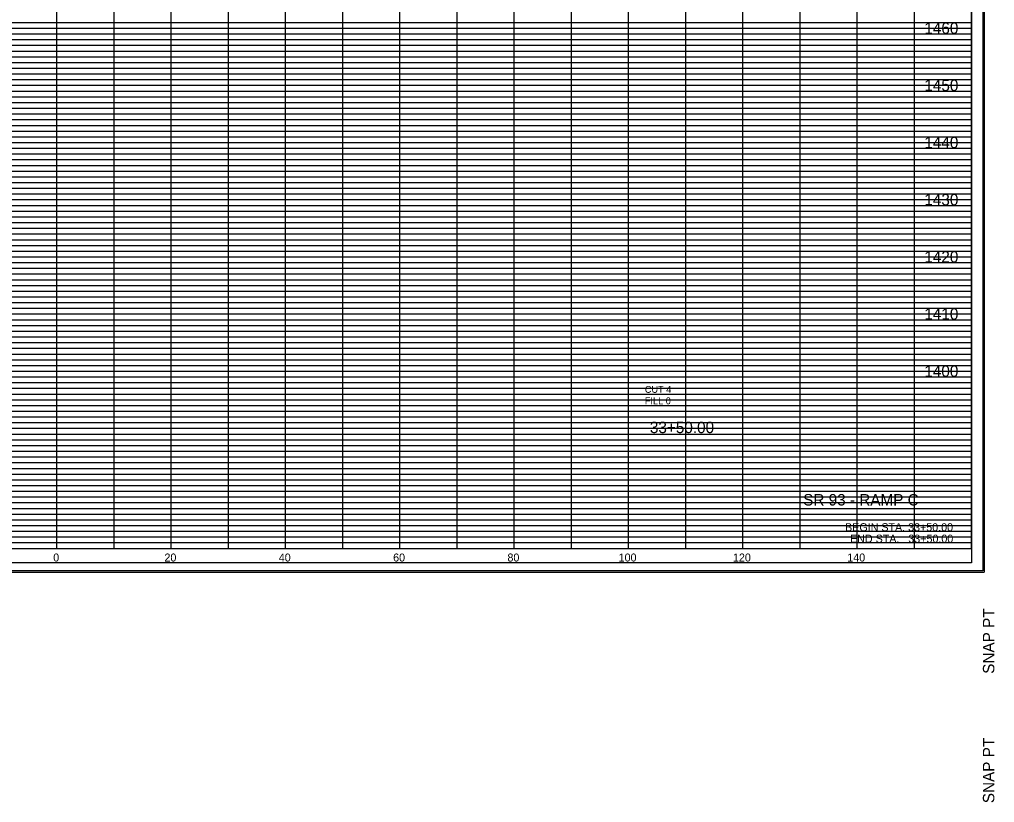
# Model space of a CAD drawing. Extents: x 980 to 2064, y 978 to 2267.
# Drawn here: x 1523.4 to 1694, y 1995.5 to 2132.5 of the extents above; entities that cross this region are included whole.
import ezdxf

# ---------------------------------------------------------------- set-up
doc = ezdxf.new("R2010")
doc.units = 0
for name, color, linetype in [('Default', 7, 'Continuous'), ('DESIGN - SHEET - Corner Text', 7, 'Continuous'), ('DESIGN - SHEET - Light Grid', 7, 'Continuous'), ('DESIGN - SHEET - Linework', 7, 'Continuous'), ('DESIGN - SHEET - Plot Shape', 7, 'Continuous'), ('DESIGN - TYPICAL - Text', 7, 'Continuous')]:
    doc.layers.add(name, color=color, linetype=linetype)

# ---------------------------------------------------------------- blocks, each defined once
blk = doc.blocks.new('XSTSHT')
at = {"layer": 'DESIGN - SHEET - Light Grid'}
for p, q in [((8, 9.2), (16, 9.2)), ((8, 9.1), (16, 9.1)), ((16, 9.2), (24, 9.2)), ((16, 9.1), (24, 9.1)), ((24, 9.2), (32, 9.2)), ((24, 9.1), (32, 9.1)), ((8, 8.9), (16, 8.9)), ((16, 8.9), (24, 8.9)), ((24, 8.9), (32, 8.9)), ((8, 8.8), (16, 8.8)), ((8, 8.7), (16, 8.7)), ((16, 8.8), (24, 8.8)), ((16, 8.7), (24, 8.7)), ((24, 8.8), (32, 8.8)), ((24, 8.7), (32, 8.7)), ((8, 8.6), (16, 8.6)), ((16, 8.6), (24, 8.6)), ((24, 8.6), (32, 8.6)), ((8, 8.5), (16, 8.5)), ((8, 8.4), (16, 8.4)), ((16, 8.5), (24, 8.5)), ((16, 8.4), (24, 8.4)), ((24, 8.5), (32, 8.5)), ((24, 8.4), (32, 8.4)), ((8, 8.3), (16, 8.3)), ((8, 8.2), (16, 8.2)), ((16, 8.3), (24, 8.3)), ((16, 8.2), (24, 8.2)), ((24, 8.3), (32, 8.3)), ((24, 8.2), (32, 8.2)), ((8, 8.1), (16, 8.1)), ((16, 8.1), (24, 8.1)), ((24, 8.1), (32, 8.1)), ((8, 7.9), (16, 7.9)), ((16, 7.9), (24, 7.9)), ((24, 7.9), (32, 7.9)), ((8, 7.8), (16, 7.8)), ((8, 7.7), (16, 7.7)), ((16, 7.8), (24, 7.8)), ((16, 7.7), (24, 7.7)), ((24, 7.8), (32, 7.8)), ((24, 7.7), (32, 7.7)), ((8, 7.6), (16, 7.6)), ((16, 7.6), (24, 7.6)), ((24, 7.6), (32, 7.6)), ((8, 7.5), (16, 7.5)), ((8, 7.4), (16, 7.4)), ((16, 7.5), (24, 7.5)), ((16, 7.4), (24, 7.4)), ((24, 7.5), (32, 7.5)), ((24, 7.4), (32, 7.4)), ((8, 7.3), (16, 7.3)), ((8, 7.2), (16, 7.2)), ((16, 7.3), (24, 7.3)), ((16, 7.2), (24, 7.2)), ((24, 7.3), (32, 7.3)), ((24, 7.2), (32, 7.2)), ((8, 7.1), (16, 7.1)), ((16, 7.1), (24, 7.1)), ((24, 7.1), (32, 7.1)), ((8, 6.9), (16, 6.9)), ((16, 6.9), (24, 6.9)), ((24, 6.9), (32, 6.9)), ((8, 6.8), (16, 6.8)), ((8, 6.7), (16, 6.7)), ((16, 6.8), (24, 6.8)), ((16, 6.7), (24, 6.7)), ((24, 6.8), (32, 6.8)), ((24, 6.7), (32, 6.7)), ((8, 6.6), (16, 6.6)), ((8, 6.5), (16, 6.5)), ((16, 6.6), (24, 6.6)), ((16, 6.5), (24, 6.5)), ((24, 6.6), (32, 6.6)), ((24, 6.5), (32, 6.5)), ((8, 6.4), (16, 6.4)), ((16, 6.4), (24, 6.4)), ((24, 6.4), (32, 6.4)), ((8, 6.3), (16, 6.3)), ((8, 6.2), (16, 6.2)), ((16, 6.3), (24, 6.3)), ((16, 6.2), (24, 6.2)), ((24, 6.3), (32, 6.3)), ((24, 6.2), (32, 6.2)), ((8, 6.1), (16, 6.1)), ((16, 6.1), (24, 6.1)), ((24, 6.1), (32, 6.1)), ((8, 5.9), (16, 5.9)), ((8, 5.8), (16, 5.8)), ((16, 5.9), (24, 5.9)), ((16, 5.8), (24, 5.8)), ((24, 5.9), (32, 5.9)), ((24, 5.8), (32, 5.8)), ((8, 5.7), (16, 5.7)), ((16, 5.7), (24, 5.7)), ((24, 5.7), (32, 5.7)), ((8, 5.6), (16, 5.6)), ((8, 5.5), (16, 5.5)), ((16, 5.6), (24, 5.6)), ((16, 5.5), (24, 5.5)), ((24, 5.6), (32, 5.6)), ((24, 5.5), (32, 5.5)), ((8, 5.4), (16, 5.4)), ((8, 5.3), (16, 5.3)), ((16, 5.4), (24, 5.4)), ((16, 5.3), (24, 5.3)), ((24, 5.4), (32, 5.4)), ((24, 5.3), (32, 5.3)), ((8, 5.2), (16, 5.2)), ((16, 5.2), (24, 5.2)), ((24, 5.2), (32, 5.2)), ((8, 5.1), (16, 5.1)), ((16, 5.1), (24, 5.1)), ((24, 5.1), (32, 5.1)), ((8, 4.9), (16, 4.9)), ((8, 4.8), (16, 4.8)), ((16, 4.9), (24, 4.9)), ((16, 4.8), (24, 4.8)), ((24, 4.9), (32, 4.9)), ((24, 4.8), (32, 4.8)), ((8, 4.7), (16, 4.7)), ((16, 4.7), (24, 4.7)), ((24, 4.7), (32, 4.7)), ((8, 4.6), (16, 4.6)), ((8, 4.5), (16, 4.5)), ((16, 4.6), (24, 4.6)), ((16, 4.5), (24, 4.5)), ((24, 4.6), (32, 4.6)), ((24, 4.5), (32, 4.5)), ((8, 4.4), (16, 4.4)), ((8, 4.3), (16, 4.3)), ((16, 4.4), (24, 4.4)), ((16, 4.3), (24, 4.3)), ((24, 4.4), (32, 4.4)), ((24, 4.3), (32, 4.3)), ((8, 4.2), (16, 4.2)), ((8, 4.1), (16, 4.1)), ((16, 4.2), (24, 4.2)), ((16, 4.1), (24, 4.1)), ((24, 4.2), (32, 4.2)), ((24, 4.1), (32, 4.1)), ((8, 3.9), (16, 3.9)), ((8, 3.8), (16, 3.8)), ((16, 3.9), (24, 3.9)), ((16, 3.8), (24, 3.8)), ((24, 3.9), (32, 3.9)), ((24, 3.8), (32, 3.8)), ((8, 3.7), (16, 3.7)), ((8, 3.6), (16, 3.6)), ((16, 3.7), (24, 3.7)), ((16, 3.6), (24, 3.6)), ((24, 3.7), (32, 3.7)), ((24, 3.6), (32, 3.6)), ((8, 3.5), (16, 3.5)), ((16, 3.5), (24, 3.5)), ((24, 3.5), (32, 3.5)), ((8, 3.4), (16, 3.4)), ((8, 3.3), (16, 3.3)), ((16, 3.4), (24, 3.4)), ((16, 3.3), (24, 3.3)), ((24, 3.4), (32, 3.4)), ((24, 3.3), (32, 3.3)), ((8, 3.2), (16, 3.2)), ((8, 3.1), (16, 3.1)), ((16, 3.2), (24, 3.2)), ((16, 3.1), (24, 3.1)), ((24, 3.2), (32, 3.2)), ((24, 3.1), (32, 3.1)), ((8, 2.9), (16, 2.9)), ((16, 2.9), (24, 2.9)), ((24, 2.9), (32, 2.9)), ((8, 2.8), (16, 2.8)), ((16, 2.8), (24, 2.8)), ((24, 2.8), (32, 2.8)), ((8, 2.7), (16, 2.7)), ((8, 2.6), (16, 2.6)), ((16, 2.7), (24, 2.7)), ((16, 2.6), (24, 2.6)), ((24, 2.7), (32, 2.7)), ((24, 2.6), (32, 2.6)), ((8, 2.5), (16, 2.5)), ((8, 2.4), (16, 2.4)), ((16, 2.5), (24, 2.5)), ((16, 2.4), (24, 2.4)), ((24, 2.5), (32, 2.5)), ((24, 2.4), (32, 2.4)), ((8, 2.3), (16, 2.3)), ((16, 2.3), (24, 2.3)), ((24, 2.3), (32, 2.3)), ((8, 2.2), (16, 2.2)), ((8, 2.1), (16, 2.1)), ((16, 2.2), (24, 2.2)), ((16, 2.1), (24, 2.1)), ((24, 2.2), (32, 2.2)), ((24, 2.1), (32, 2.1)), ((8, 1.9), (16, 1.9)), ((16, 1.9), (24, 1.9)), ((24, 1.9), (32, 1.9)), ((8, 1.8), (16, 1.8)), ((16, 1.8), (24, 1.8)), ((24, 1.8), (32, 1.8)), ((8, 1.7), (16, 1.7)), ((8, 1.6), (16, 1.6)), ((16, 1.7), (24, 1.7)), ((16, 1.6), (24, 1.6)), ((24, 1.7), (32, 1.7)), ((24, 1.6), (32, 1.6)), ((8, 1.5), (16, 1.5)), ((8, 1.4), (16, 1.4)), ((16, 1.5), (24, 1.5)), ((16, 1.4), (24, 1.4)), ((24, 1.5), (32, 1.5)), ((24, 1.4), (32, 1.4)), ((8, 1.3), (16, 1.3)), ((8, 1.2), (16, 1.2)), ((16, 1.3), (24, 1.3)), ((16, 1.2), (24, 1.2)), ((24, 1.3), (32, 1.3)), ((24, 1.2), (32, 1.2)), ((8, 1.1), (16, 1.1)), ((16, 1.1), (24, 1.1)), ((24, 1.1), (32, 1.1)), ((8, 0.9), (16, 0.9)), ((16, 0.9), (24, 0.9)), ((24, 0.9), (32, 0.9)), ((8, 0.8), (16, 0.8)), ((8, 0.7), (16, 0.7)), ((16, 0.8), (24, 0.8)), ((16, 0.7), (24, 0.7)), ((24, 0.8), (32, 0.8)), ((24, 0.7), (32, 0.7)), ((8, 0.6), (16, 0.6)), ((16, 0.6), (24, 0.6)), ((24, 0.6), (32, 0.6)), ((8, 0.5), (16, 0.5)), ((8, 0.4), (16, 0.4)), ((16, 0.5), (24, 0.5)), ((16, 0.4), (24, 0.4)), ((24, 0.5), (32, 0.5)), ((24, 0.4), (32, 0.4)), ((8, 0.3), (16, 0.3)), ((8, 0.2), (16, 0.2)), ((16, 0.3), (24, 0.3)), ((16, 0.2), (24, 0.2)), ((24, 0.3), (32, 0.3)), ((24, 0.2), (32, 0.2)), ((8, 0.1), (16, 0.1)), ((16, 0.1), (24, 0.1)), ((24, 0.1), (32, 0.1))]:
    blk.add_line(p, q, dxfattribs=at)
at = {"layer": 'DESIGN - SHEET - Linework'}
for p, q in [((32.217, 21.414), (32.217, -0.414)), ((16, 0), (16, 21)), ((17, 0), (17, 21)), ((18, 0), (18, 21)), ((19, 0), (19, 21)), ((20, 0), (20, 21)), ((21, 0), (21, 21)), ((22, 0), (22, 21)), ((23, 0), (23, 21)), ((24, 0), (24, 21)), ((25, 0), (25, 21)), ((26, 0), (26, 21)), ((27, 0), (27, 21)), ((28, 0), (28, 20)), ((29, 0), (29, 20)), ((30, 0), (30, 20)), ((31, 0), (31, 20)), ((0, 9), (32, 9)), ((0, 8), (32, 8)), ((0, 7), (32, 7)), ((0, 6), (32, 6)), ((0, 5), (32, 5)), ((0, 4), (32, 4)), ((0, 3), (32, 3)), ((0, 2), (32, 2)), ((0, 1), (32, 1)), ((-1.823, -0.414), (32.217, -0.414))]:
    blk.add_line(p, q, dxfattribs=at)
blk.add_lwpolyline([(0, 21), (0, 0), (32, 0), (32, 21), (0, 21)], dxfattribs=at)
at = {"layer": 'DESIGN - SHEET - Plot Shape'}
for points in [[(-1.803, 21.394), (32.197, 21.394), (32.197, -0.394), (-1.803, -0.394)], [(-0.85, 21), (32, 21), (32, -0.25), (-0.85, -0.25)]]:
    blk.add_lwpolyline(points, close=True, dxfattribs=at)
at = {"layer": 'DESIGN - SHEET - Corner Text'}
for s, p in [('  SNAP PT', (32.397, 21.394)), ('SNAP PT  ', (32.397, -2.194))]:
    blk.add_text(s, height=0.2, rotation=90, dxfattribs=at).set_placement(p)

msp = doc.modelspace()

# ---------------------------------------------------------------- block references
at = {"layer": 'Default', "xscale": 10, "yscale": 10}
for p in [(1370, 2040), (1370, 1780)]:
    msp.add_blockref('XSTSHT', p, dxfattribs=at)

# ---------------------------------------------------------------- texts
at = {"layer": 'Default'}
for s, height, p in [('     1460     ', 2, (1678.01, 2130)), ('     1450     ', 2, (1678.01, 2120)), ('     1440     ', 2, (1678.01, 2110)), ('     1430     ', 2, (1678.01, 2100)), ('     1420     ', 2, (1678.01, 2090)), ('     1410     ', 2, (1678.01, 2080)), ('     1400     ', 2, (1678.01, 2070)), ('     33+50.00     ', 2, (1630, 2060.16)), ('     0     ', 1.4, (1526.74, 2037.7)), ('     0     ', 1.4, (1526.74, 2037.7)), ('     20     ', 1.4, (1546.2, 2037.7)), ('     40     ', 1.4, (1566.2, 2037.7)), ('     60     ', 1.4, (1586.2, 2037.7)), ('     80     ', 1.4, (1606.2, 2037.7)), ('     100     ', 1.4, (1625.65, 2037.7)), ('     120     ', 1.4, (1645.65, 2037.7)), ('     140     ', 1.4, (1665.65, 2037.7))]:
    msp.add_text(s, height=height, dxfattribs=at).set_placement(p)
at = {"layer": 'DESIGN - SHEET - Corner Text'}
for s, height, p in [('SR 93 - RAMP C', 2, (1660.53, 2047.5)), ('BEGIN STA. 33+50.00', 1.4, (1667.86, 2043)), ('END STA.   33+50.00', 1.4, (1668.73, 2041))]:
    msp.add_text(s, height=height, dxfattribs=at).set_placement(p)
at = {"layer": 'DESIGN - TYPICAL - Text'}
for s, p in [('CUT 4', (1632.83, 2067.21)), ('FILL 0', (1632.83, 2065.21))]:
    msp.add_text(s, height=1.2, dxfattribs=at).set_placement(p)

doc.saveas('drawing.dxf')
